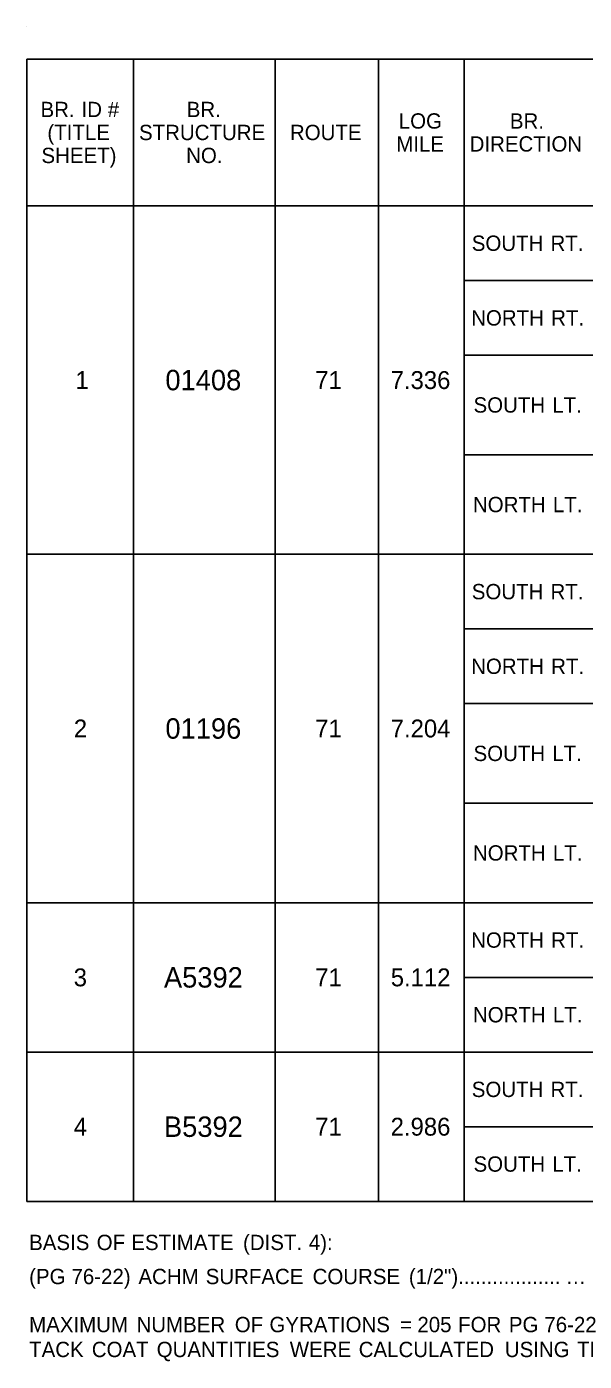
# Model space of a CAD drawing. Extents: x 540541 to 1930787, y -1948574 to 596640.
# Drawn here: x 555955 to 556174, y -1946758 to -1946235 of the extents above; entities that cross this region are included whole.
import ezdxf

# ---------------------------------------------------------------- set-up
doc = ezdxf.new("R2010")
doc.units = 0
doc.layers.add('Default', color=7, linetype='Continuous')
doc.layers.add('R_Border', color=7, linetype='Continuous')

msp = doc.modelspace()

# ---------------------------------------------------------------- linework, layer by layer
at = {"layer": 'Default'}
for p, q in [((555955.32, -1946247.69), (556842.08, -1946247.69)), ((555955.32, -1946695.21), (555955.32, -1946247.69)), ((555997.24, -1946695.21), (555997.24, -1946247.69)), ((556052.82, -1946695.21), (556052.82, -1946247.69)), ((556093.28, -1946695.21), (556093.28, -1946247.69)), ((556126.92, -1946695.21), (556126.92, -1946247.69)), ((555955.32, -1946305.21), (556373.11, -1946305.21)), ((556052.82, -1946578.21), (556052.82, -1946305.21)), ((556126.92, -1946334.46), (556842.08, -1946334.46)), ((556126.92, -1946363.71), (556842.08, -1946363.71)), ((556126.92, -1946402.71), (556474.99, -1946402.71)), ((555955.32, -1946441.71), (555997.24, -1946441.71)), ((555955.32, -1946441.71), (556323.38, -1946441.71)), ((556052.82, -1946441.71), (556126.92, -1946441.71)), ((556126.92, -1946441.71), (556842.08, -1946441.71)), ((556126.92, -1946470.96), (556323.38, -1946470.96)), ((556126.92, -1946500.21), (556842.08, -1946500.21)), ((556126.92, -1946539.21), (556474.99, -1946539.21)), ((555955.32, -1946578.21), (556176.64, -1946578.21)), ((555955.32, -1946578.21), (556126.92, -1946578.21)), ((556126.92, -1946578.21), (556842.08, -1946578.21)), ((556126.92, -1946607.46), (556842.08, -1946607.46)), ((555955.32, -1946636.71), (556842.08, -1946636.71)), ((556052.82, -1946695.21), (556052.82, -1946636.71)), ((556126.92, -1946665.96), (556842.08, -1946665.96)), ((555955.32, -1946695.21), (556842.08, -1946695.21))]:
    msp.add_line(p, q, dxfattribs=at)
at = {"layer": 'R_Border'}
msp.add_line((555955.32, -1946235.01), (555955.32, -1946235.01), dxfattribs=at)

# ---------------------------------------------------------------- texts
at = {"layer": 'Default'}
for s, height, p in [('BR.', 6, (555960.76, -1946270.45)), (' ID', 6, (555974.62, -1946270.45)), ('BR.', 6, (556018.1, -1946270.45)), (' #', 6, (555984.91, -1946270.45)), ('LOG', 6, (556101.27, -1946274.95)), ('BR.', 6, (556144.85, -1946274.95)), ('(TITLE', 6, (555963.45, -1946279.45)), ('STRUCTURE', 6, (555999.39, -1946279.45)), ('ROUTE', 6, (556058.58, -1946279.45)), ('MILE', 6, (556100.29, -1946283.95)), ('DIRECTION', 6, (556129.06, -1946283.95)), ('SHEET)', 6, (555961.12, -1946288.45)), ('NO.', 6, (556017.87, -1946288.45)), ('SOUTH', 6, (556129.9, -1946322.84)), (' RT.', 6, (556158.56, -1946322.84)), ('NORTH', 6, (556129.66, -1946352.09)), (' RT.', 6, (556158.8, -1946352.09)), ('1', 7, (555974.46, -1946376.96)), ('01408', 8, (556009.74, -1946377.46)), ('71', 7, (556068.51, -1946376.96)), ('7.336', 7, (556098.09, -1946376.96)), ('SOUTH', 6, (556130.59, -1946386.21)), (' LT.', 6, (556159.26, -1946386.21)), ('NORTH', 6, (556130.36, -1946425.21)), (' LT.', 6, (556159.49, -1946425.21)), ('SOUTH', 6, (556129.9, -1946459.34)), (' RT.', 6, (556158.56, -1946459.34)), ('NORTH', 6, (556129.66, -1946488.59)), (' RT.', 6, (556158.8, -1946488.59)), ('2', 7, (555973.82, -1946513.46)), ('01196', 8, (556009.75, -1946513.96)), ('71', 7, (556068.51, -1946513.46)), ('7.204', 7, (556098.11, -1946513.46)), ('SOUTH', 6, (556130.59, -1946522.71)), (' LT.', 6, (556159.26, -1946522.71)), ('NORTH', 6, (556130.36, -1946561.71)), (' LT.', 6, (556159.49, -1946561.71)), ('NORTH', 6, (556129.66, -1946595.84)), (' RT.', 6, (556158.8, -1946595.84)), ('3', 7, (555973.78, -1946610.96)), ('A5392', 8, (556009.17, -1946611.46)), ('71', 7, (556068.51, -1946610.96)), ('5.112', 7, (556098.13, -1946610.96)), ('NORTH', 6, (556130.36, -1946625.09)), (' LT.', 6, (556159.49, -1946625.09)), ('SOUTH', 6, (556129.9, -1946654.34)), (' RT.', 6, (556158.56, -1946654.34)), ('4', 7, (555973.8, -1946669.46)), ('B5392', 8, (556009.17, -1946669.96)), ('71', 7, (556068.51, -1946669.46)), ('2.986', 7, (556098.09, -1946669.46)), ('SOUTH', 6, (556130.59, -1946683.59)), (' LT.', 6, (556159.26, -1946683.59)), ('BASIS', 6, (555956.29, -1946714.3)), (' OF', 6, (555980.55, -1946714.3)), (' ESTIMATE', 6, (555994.14, -1946714.3)), (' (DIST.', 6, (556037.95, -1946714.3)), (' 4):', 6, (556063.76, -1946714.3)), ('(PG', 6, (555956.29, -1946727.65)), (' 76-22)', 6, (555970.67, -1946727.65)), (' ACHM', 6, (555996.92, -1946727.65)), (' SURFACE', 6, (556023.3, -1946727.65)), (' COURSE', 6, (556065.24, -1946727.65)), (' (1/2")..................', 6, (556103, -1946727.65)), ('…', 6, (556166.7, -1946727.65)), ('MAXIMUM', 6, (555956.29, -1946746.48)), (' NUMBER', 6, (555996.18, -1946746.48)), (' OF', 6, (556034.73, -1946746.48)), (' GYRATIONS', 6, (556048.31, -1946746.48)), (' =', 6, (556099.58, -1946746.48)), (' 205', 6, (556106.34, -1946746.48)), (' FOR', 6, (556122.31, -1946746.48)), (' PG', 6, (556142.22, -1946746.48)), (' 76-22', 6, (556156.14, -1946746.48)), ('TACK', 6, (555956.29, -1946756.23)), (' COAT', 6, (555978.64, -1946756.23)), (' QUANTITIES', 6, (556004.09, -1946756.23)), (' WERE', 6, (556056.29, -1946756.23)), (' CALCULATED', 6, (556083.32, -1946756.23)), (' USING', 6, (556140.64, -1946756.23)), (' THE', 6, (556168.99, -1946756.23))]:
    msp.add_text(s, height=height, dxfattribs=at).set_placement(p)

doc.saveas('drawing.dxf')
